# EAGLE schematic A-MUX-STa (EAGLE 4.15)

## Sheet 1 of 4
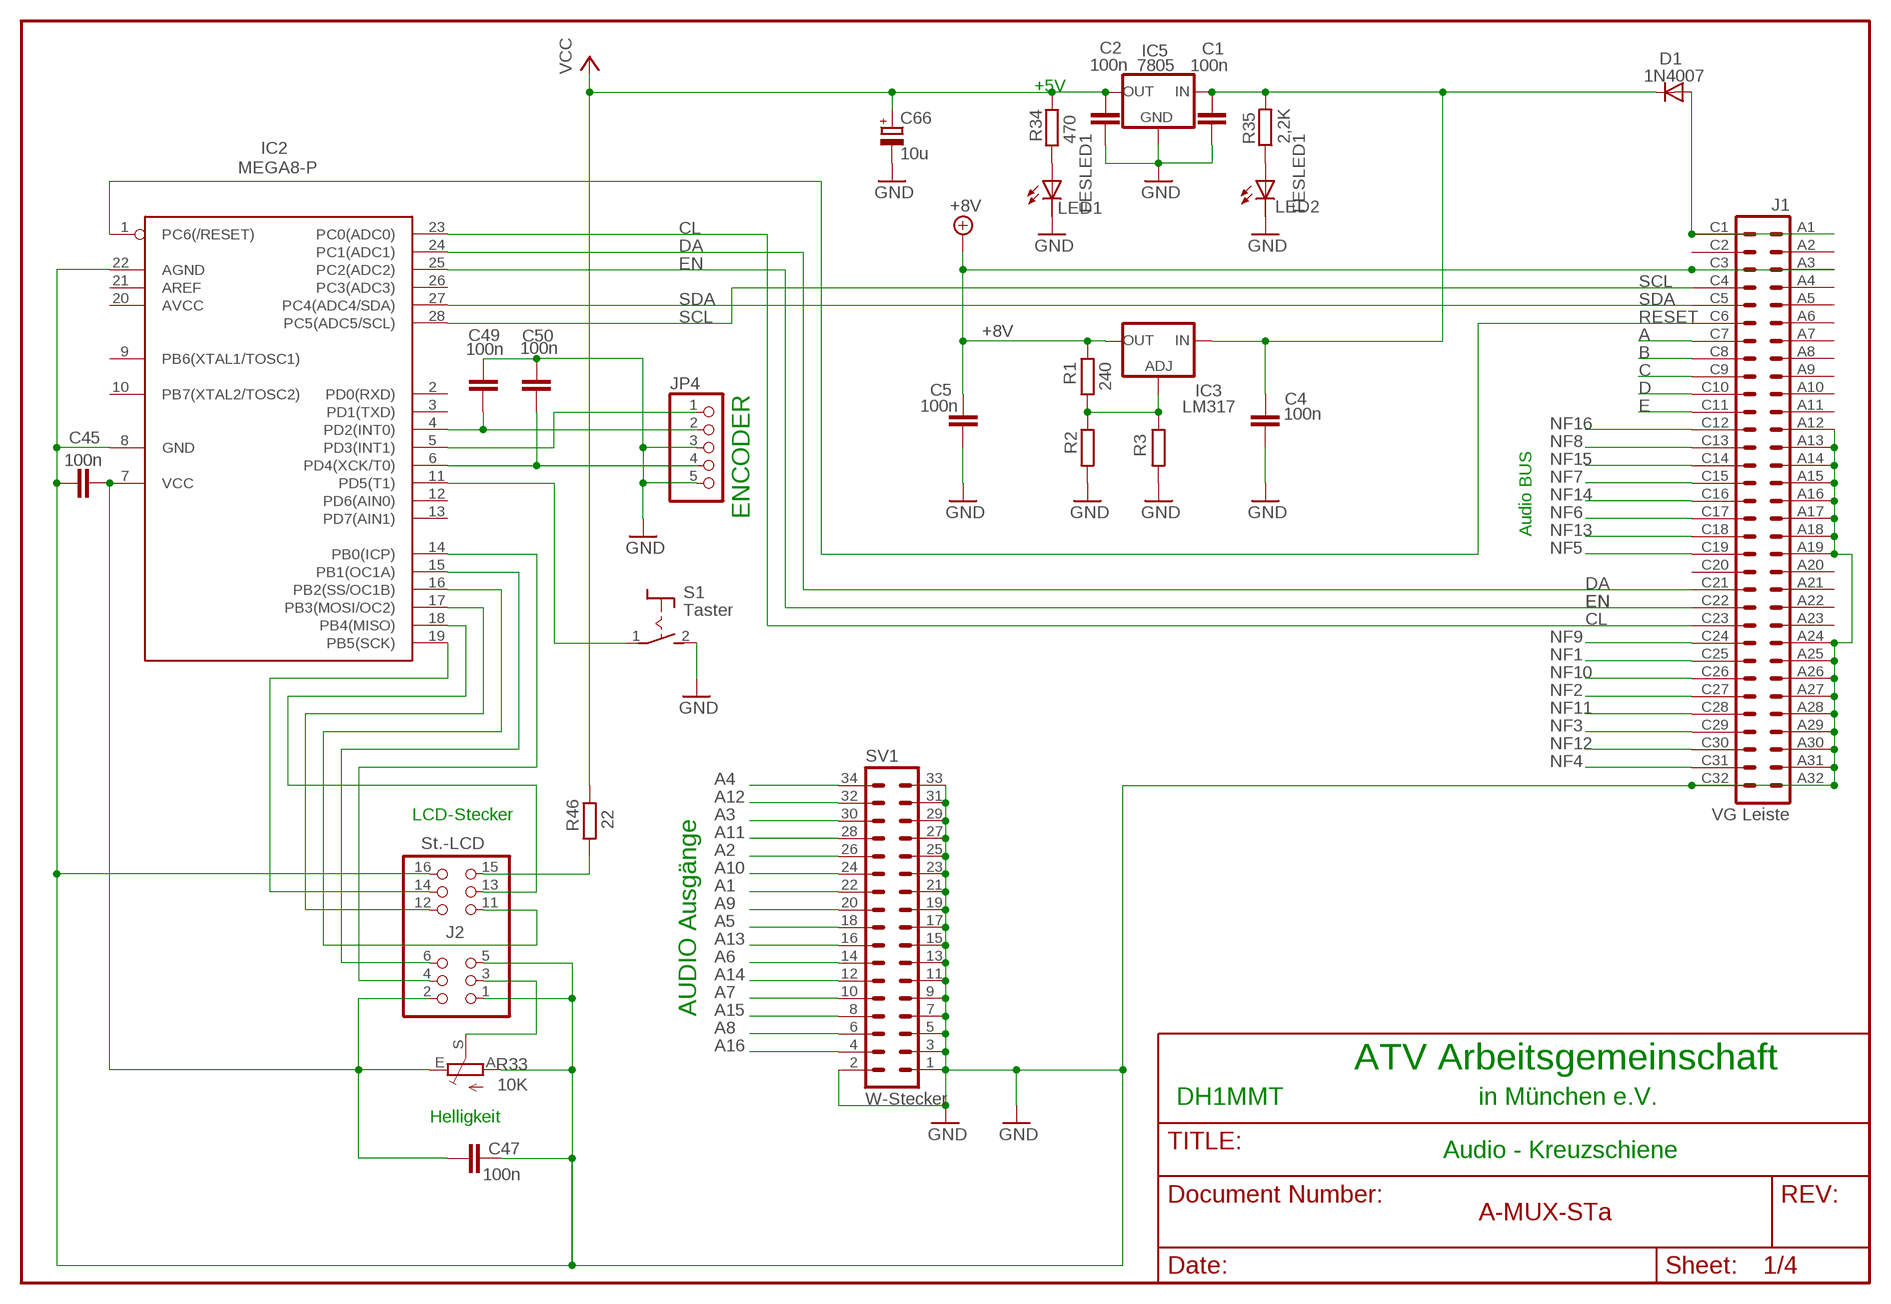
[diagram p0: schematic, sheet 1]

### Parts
C1  100n  C-EUC0805K  [C0805K]
C2  100n  C-EUC0805K  [C0805K]
C4  100n  C-EUC0805K  [C0805K]
C5  100n  C-EUC0805K  [C0805K]
C45  100n  C-EU025-024X044  [C025-024X044]
C47  100n  C-EU025-024X044  [C025-024X044]
C49  100n  C-EUC0805K  [C0805K]
C50  100n  C-EUC0805K  [C0805K]
C66  10u  CPOL-EUE2.5-5  [E2,5-5]
D1  1N4007  DIODE-D-7.5  [D-7.5]
IC2  MEGA8-P  [DIL28-3]
IC3  LM317  LM317TL  [317TL]
IC5  7805  78XXL  [78XXL]
J1  VG Leiste  VG64P  [VG64P]
J2  St.-LCD  PINHD2X3-2X3  [2X3-2X3]
JP4  PINHD-1X5  [1X05]
LED1  FESLED1  [FESLED1]
LED2  FESLED1  [FESLED1]
R1  240  R-EU_MELF0204W  [MINI_MELF-0204W]
R2  R-EU_MELF0204W  [MINI_MELF-0204W]
R3  R-EU_MELF0204W  [MINI_MELF-0204W]
R33  10K  TRIM_EU-CA6V  [CA6V]
R34  470  R-EU_0204/7  [0204/7]
R35  2,2K  R-EU_0204/7  [0204/7]
R46  22  R-EU_0204/7  [0204/7]
S1  Taster  MARQ  [MARQ]
SV1  W-Stecker  ML34  [ML34]

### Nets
+8V: C5.1 IC3.2(OUT) J1.A3 J1.C3 R1.1 ; also sheet 3,4
A: J1.C7
A1: SV1.22 ; also sheet 3
A2: SV1.26 ; also sheet 3
A3: SV1.30 ; also sheet 3
A4: SV1.34 ; also sheet 3
A5: SV1.18 ; also sheet 3
A6: SV1.14 ; also sheet 3
A7: SV1.10 ; also sheet 3
A8: SV1.6 ; also sheet 3
A9: SV1.20 ; also sheet 4
A10: SV1.24 ; also sheet 4
A11: SV1.28 ; also sheet 4
A12: SV1.32 ; also sheet 4
A13: SV1.16 ; also sheet 4
A14: SV1.12 ; also sheet 4
A15: SV1.8 ; also sheet 4
A16: SV1.4 ; also sheet 4
B: J1.C8
C: J1.C9
CL: IC2.23(PC0(ADC0)) J1.C23
D: J1.C10
DA: IC2.24(PC1(ADC1)) J1.C21
E: J1.C11
EN: IC2.25(PC2(ADC2)) J1.C22
GND: C1.2 C2.2 C4.2 C5.2 C45.1 C47.2 C49.1 C50.1 C66.- IC2.8(GND) IC2.22(AGND) IC5.GND J1.A12 J1.A13 J1.A14 J1.A15 J1.A16 J1.A17 J1.A18 J1.A19 J1.A24 J1.A25 J1.A26 J1.A27 J1.A28 J1.A29 J1.A30 J1.A31 J1.A32 J1.C32 J2.1 J2.5 J2.16 JP4.3 JP4.5 LED1.K(C) LED2.K(C) R2.2 R3.2 R33.A S1.2(S) SV1.1 SV1.2 SV1.3 SV1.5 SV1.7 SV1.9 SV1.11 SV1.13 SV1.15 SV1.17 SV1.19 SV1.21 SV1.23 SV1.25 SV1.27 SV1.29 SV1.31 SV1.33 ; also sheet 2,3,4
N$2: C1.1 C4.1 D1.C IC3.3(IN) IC5.IN R35.2
N$5: J2.15 R46.2
N$7: IC2.11(PD5(T1)) S1.1(P)
N$10: C49.2 IC2.4(PD2(INT0)) JP4.2
N$11: C50.2 IC2.6(PD4(XCK/T0)) JP4.4
N$12: D1.A J1.A1 J1.C1
N$15: IC3.1(ADJ) R1.2 R2.1 R3.1
N$56: IC2.15(PB1(OC1A)) J2.6
N$57: IC2.16(PB2(SS/OC1B)) J2.11
N$59: IC2.17(PB3(MOSI/OC2)) J2.12
N$61: IC2.18(PB4(MISO)) J2.13
N$62: IC2.19(PB5(SCK)) J2.14
N$70: LED1.A R34.2
N$89: J2.3 R33.S
N$91: LED2.A R35.1
N$142: IC2.14(PB0(ICP)) J2.4
N$236: IC2.5(PD3(INT1)) JP4.1
NF1: J1.C25 ; also sheet 3
NF2: J1.C27 ; also sheet 3
NF3: J1.C29 ; also sheet 3
NF4: J1.C31 ; also sheet 3
NF5: J1.C19 ; also sheet 3
NF6: J1.C17 ; also sheet 3
NF7: J1.C15 ; also sheet 3
NF8: J1.C13 ; also sheet 3
NF9: J1.C24 ; also sheet 4
NF10: J1.C26 ; also sheet 4
NF11: J1.C28 ; also sheet 4
NF12: J1.C30 ; also sheet 4
NF13: J1.C18 ; also sheet 4
NF14: J1.C16 ; also sheet 4
NF15: J1.C14 ; also sheet 4
NF16: J1.C12 ; also sheet 4
RESET: IC2.1(PC6(/RESET)) J1.C6
SCL: IC2.28(PC5(ADC5/SCL)) J1.C4 ; also sheet 2
SDA: IC2.27(PC4(ADC4/SDA)) J1.C5 ; also sheet 2
VCC: C2.1 C45.2 C47.1 C66.+ IC2.7(VCC) IC5.OUT J2.2 R33.E R34.1 R46.1 ; also sheet 2
Unconnected: IC2.2(PD0(RXD)) IC2.3(PD1(TXD)) IC2.9(PB6(XTAL1/TOSC1)) IC2.10(PB7(XTAL2/TOSC2)) IC2.12(PD6(AIN0)) IC2.13(PD7(AIN1)) IC2.20(AVCC) IC2.21(AREF) IC2.26(PC3(ADC3)) J1.A2 J1.A4 J1.A5 J1.A6 J1.A7 J1.A8 J1.A9 J1.A10 J1.A11 J1.A20 J1.A21 J1.A22 J1.A23 J1.C2 J1.C20

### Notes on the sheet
- +5V
- ENCODER
- Audio BUS
- LCD-Stecker
- AUDIO Ausgänge
- ATV Arbeitsgemeinschaft
- DH1MMT | in München e.V.
- Helligkeit
- Audio - Kreuzschiene

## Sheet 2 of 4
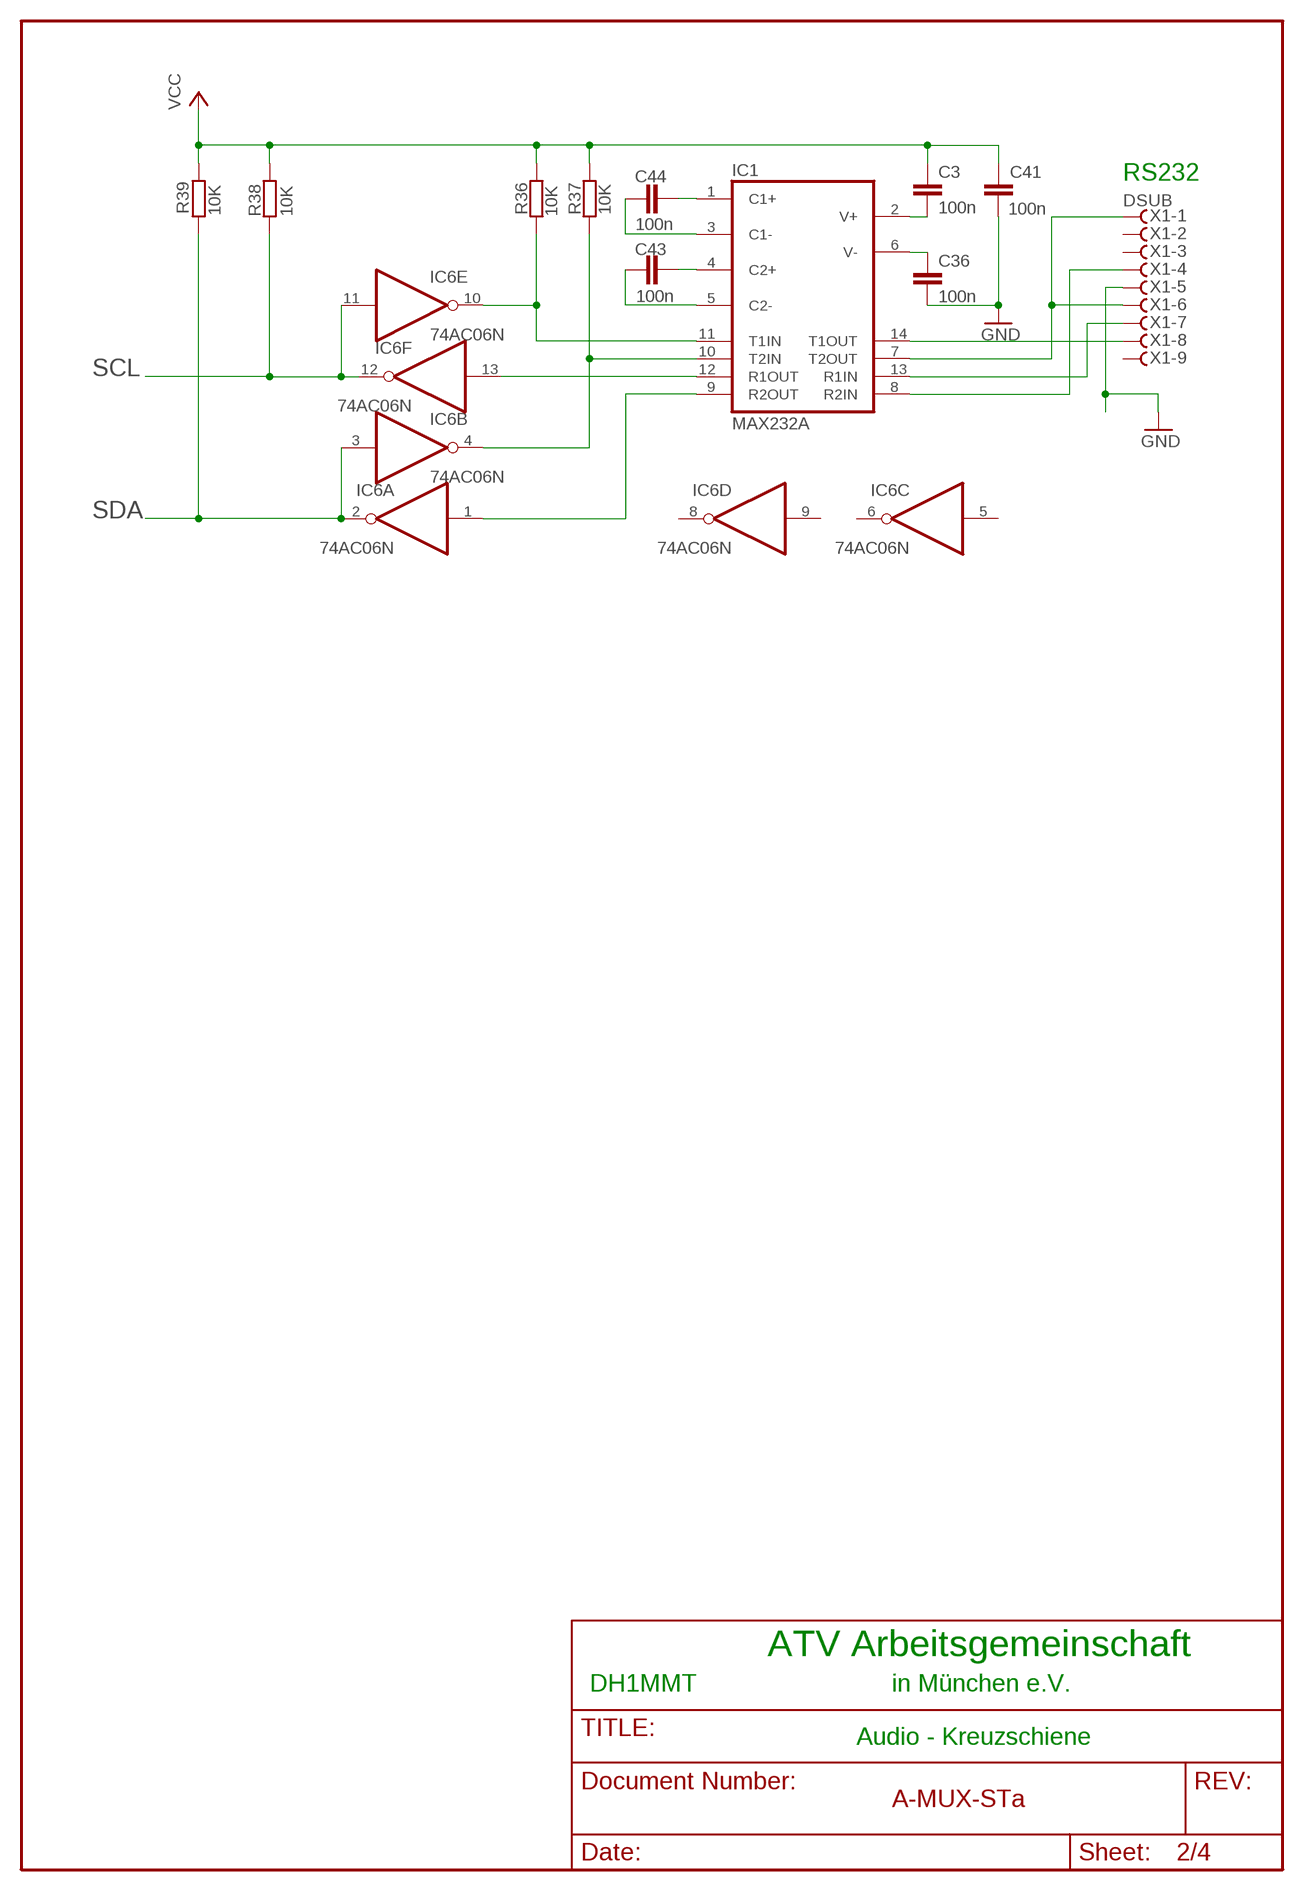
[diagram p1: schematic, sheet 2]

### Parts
C3  100n  C-EU050-024X044  [C050-024X044]
C36  100n  C-EU025-024X044  [C025-024X044]
C41  100n  C-EU050-024X044  [C050-024X044]
C43  100n  C-EU025-024X044  [C025-024X044]
C44  100n  C-EU050-024X044  [C050-024X044]
IC1  MAX232A  MAX232  [DIL16]
IC6  74AC06N  [DIL14]
R36  10K  R-EU_0204/7  [0204/7]
R37  10K  R-EU_0204/7  [0204/7]
R38  10K  R-EU_0204/7  [0204/7]
R39  10K  R-EU_0204/7  [0204/7]
X1  DSUB  F09HS  [F09H]

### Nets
GND: C36.2 C41.1 X1.5 ; also sheet 1,3,4
N$126: IC1.12(R1OUT) IC6.13(F:I)
N$127: C44.2 IC1.1(C1+)
N$129: C44.1 IC1.3(C1-)
N$130: C43.2 IC1.4(C2+)
N$131: C43.1 IC1.5(C2-)
N$132: C3.2 IC1.2(V+)
N$133: C36.1 IC1.6(V-)
N$134: IC1.9(R2OUT) IC6.1(A:I)
N$135: IC1.11(T1IN) IC6.10(E:O) R36.1
N$136: IC1.14(T1OUT) X1.8
N$137: IC1.13(R1IN) X1.7
N$138: IC1.8(R2IN) X1.4
N$139: IC1.7(T2OUT) X1.1 X1.6
N$145: IC1.10(T2IN) IC6.4(B:O) R37.1
SCL: IC6.11(E:I) IC6.12(F:O) R38.1 ; also sheet 1
SDA: IC6.2(A:O) IC6.3(B:I) R39.1 ; also sheet 1
VCC: C3.1 C41.2 R36.2 R37.2 R38.2 R39.2 ; also sheet 1
Unconnected: IC6.5(C:I) IC6.6(C:O) IC6.8(D:O) IC6.9(D:I) X1.2 X1.3 X1.9

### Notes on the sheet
- RS232
- ATV Arbeitsgemeinschaft
- DH1MMT | in München e.V.
- Audio - Kreuzschiene

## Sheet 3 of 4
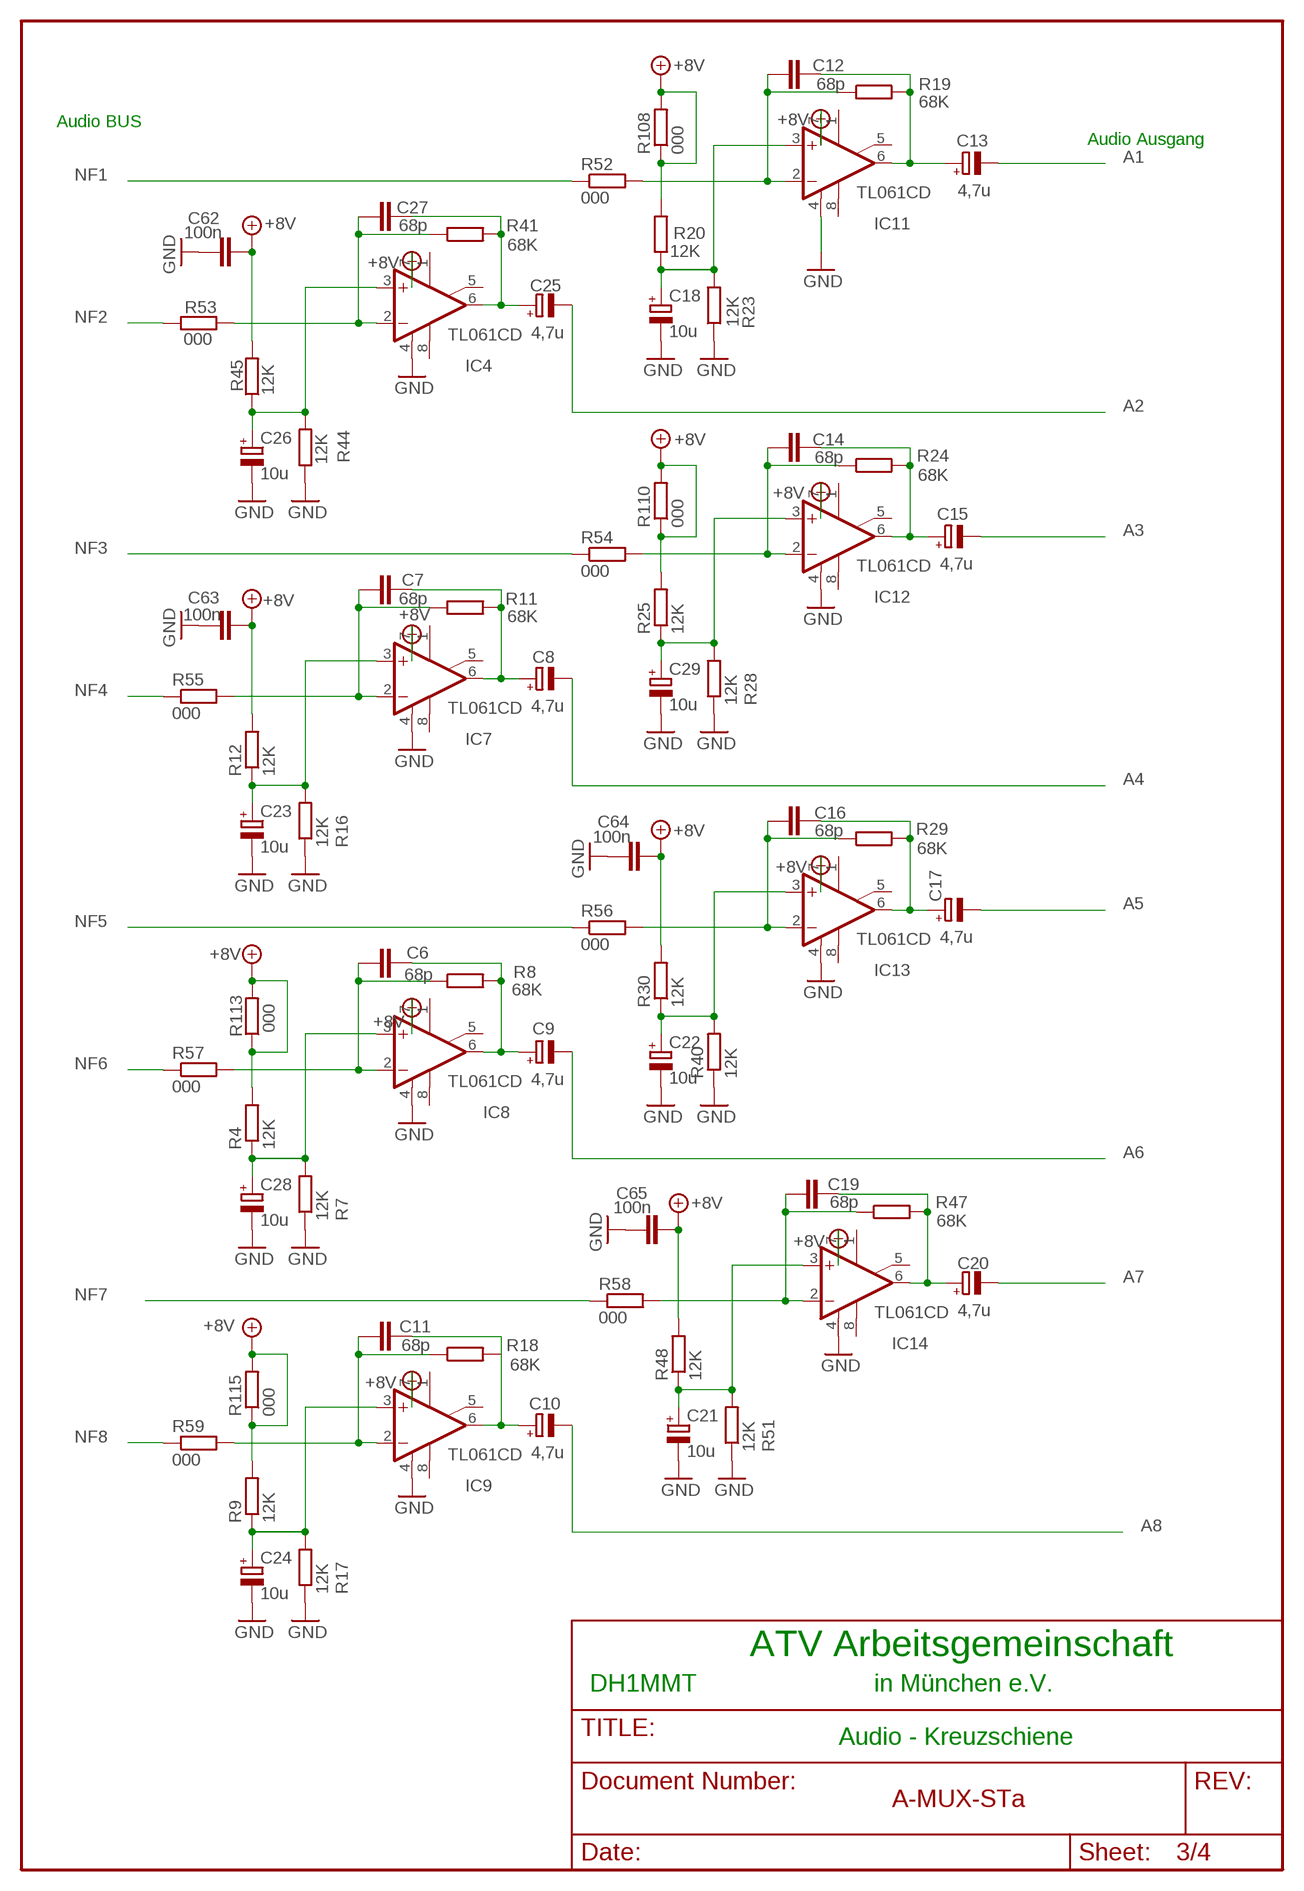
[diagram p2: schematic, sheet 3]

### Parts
C6  68p  C-EUC0805K  [C0805K]
C7  68p  C-EUC0805K  [C0805K]
C8  4,7u  CPOL-EUE2.5-5  [E2,5-5]
C9  4,7u  CPOL-EUE2.5-5  [E2,5-5]
C10  4,7u  CPOL-EUE2.5-5  [E2,5-5]
C11  68p  C-EUC0805K  [C0805K]
C12  68p  C-EUC0805K  [C0805K]
C13  4,7u  CPOL-EUE2.5-5  [E2,5-5]
C14  68p  C-EUC0805K  [C0805K]
C15  4,7u  CPOL-EUE2.5-5  [E2,5-5]
C16  68p  C-EUC0805K  [C0805K]
C17  4,7u  CPOL-EUE2.5-5  [E2,5-5]
C18  10u  CPOL-EUE2.5-5  [E2,5-5]
C19  68p  C-EUC0805K  [C0805K]
C20  4,7u  CPOL-EUE2.5-5  [E2,5-5]
C21  10u  CPOL-EUE2.5-5  [E2,5-5]
C22  10u  CPOL-EUE2.5-5  [E2,5-5]
C23  10u  CPOL-EUE2.5-5  [E2,5-5]
C24  10u  CPOL-EUE2.5-5  [E2,5-5]
C25  4,7u  CPOL-EUE2.5-5  [E2,5-5]
C26  10u  CPOL-EUE2.5-5  [E2,5-5]
C27  68p  C-EUC0805K  [C0805K]
C28  10u  CPOL-EUE2.5-5  [E2,5-5]
C29  10u  CPOL-EUE2.5-5  [E2,5-5]
C62  100n  C-EUC0805K  [C0805K]
C63  100n  C-EUC0805K  [C0805K]
C64  100n  C-EUC0805K  [C0805K]
C65  100n  C-EUC0805K  [C0805K]
IC4  TL061CD  TL061D  [SO08]
IC7  TL061CD  TL061D  [SO08]
IC8  TL061CD  TL061D  [SO08]
IC9  TL061CD  TL061D  [SO08]
IC11  TL061CD  TL061D  [SO08]
IC12  TL061CD  TL061D  [SO08]
IC13  TL061CD  TL061D  [SO08]
IC14  TL061CD  TL061D  [SO08]
R4  12K  R-EU_MELF0204W  [MINI_MELF-0204W]
R7  12K  R-EU_MELF0204W  [MINI_MELF-0204W]
R8  68K  R-EU_MELF0204W  [MINI_MELF-0204W]
R9  12K  R-EU_MELF0204W  [MINI_MELF-0204W]
R11  68K  R-EU_MELF0204W  [MINI_MELF-0204W]
R12  12K  R-EU_MELF0204W  [MINI_MELF-0204W]
R16  12K  R-EU_MELF0204W  [MINI_MELF-0204W]
R17  12K  R-EU_MELF0204W  [MINI_MELF-0204W]
R18  68K  R-EU_MELF0204W  [MINI_MELF-0204W]
R19  68K  R-EU_MELF0204W  [MINI_MELF-0204W]
R20  12K  R-EU_MELF0204W  [MINI_MELF-0204W]
R23  12K  R-EU_MELF0204W  [MINI_MELF-0204W]
R24  68K  R-EU_MELF0204W  [MINI_MELF-0204W]
R25  12K  R-EU_MELF0204W  [MINI_MELF-0204W]
R28  12K  R-EU_MELF0204W  [MINI_MELF-0204W]
R29  68K  R-EU_MELF0204W  [MINI_MELF-0204W]
R30  12K  R-EU_MELF0204W  [MINI_MELF-0204W]
R40  12K  R-EU_MELF0204W  [MINI_MELF-0204W]
R41  68K  R-EU_MELF0204W  [MINI_MELF-0204W]
R44  12K  R-EU_MELF0204W  [MINI_MELF-0204W]
R45  12K  R-EU_MELF0204W  [MINI_MELF-0204W]
R47  68K  R-EU_MELF0204W  [MINI_MELF-0204W]
R48  12K  R-EU_MELF0204W  [MINI_MELF-0204W]
R51  12K  R-EU_MELF0204W  [MINI_MELF-0204W]
R52  000  R-EU_MELF0204W  [MINI_MELF-0204W]
R53  000  R-EU_MELF0204W  [MINI_MELF-0204W]
R54  000  R-EU_MELF0204W  [MINI_MELF-0204W]
R55  000  R-EU_MELF0204W  [MINI_MELF-0204W]
R56  000  R-EU_MELF0204W  [MINI_MELF-0204W]
R57  000  R-EU_MELF0204W  [MINI_MELF-0204W]
R58  000  R-EU_MELF0204W  [MINI_MELF-0204W]
R59  000  R-EU_MELF0204W  [MINI_MELF-0204W]
R108  000  R-EU_MELF0204W  [MINI_MELF-0204W]
R110  000  R-EU_MELF0204W  [MINI_MELF-0204W]
R113  000  R-EU_MELF0204W  [MINI_MELF-0204W]
R115  000  R-EU_MELF0204W  [MINI_MELF-0204W]

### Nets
+8V: C62.2 C63.2 C64.2 C65.2 IC4.7(V+) IC7.7(V+) IC8.7(V+) IC9.7(V+) IC11.7(V+) IC12.7(V+) IC13.7(V+) IC14.7(V+) R4.2 R9.2 R12.2 R20.2 R25.2 R30.2 R45.2 R48.2 R108.1 R108.2 R110.1 R110.2 R113.1 R113.2 R115.1 R115.2 ; also sheet 1,4
A1: C13.- ; also sheet 1
A2: C25.- ; also sheet 1
A3: C15.- ; also sheet 1
A4: C8.- ; also sheet 1
A5: C17.- ; also sheet 1
A6: C9.- ; also sheet 1
A7: C20.- ; also sheet 1
A8: C10.- ; also sheet 1
GND: C18.- C21.- C22.- C23.- C24.- C26.- C28.- C29.- C62.1 C63.1 C64.1 C65.1 IC4.4(V-) IC7.4(V-) IC8.4(V-) IC9.4(V-) IC11.4(V-) IC12.4(V-) IC13.4(V-) IC14.4(V-) R7.1 R16.1 R17.1 R23.1 R28.1 R40.1 R44.1 R51.1 ; also sheet 1,2,4
N$9: C25.+ C27.2 IC4.6(OUT) R41.2
N$13: C7.2 C8.+ IC7.6(OUT) R11.2
N$14: C28.+ IC8.3(+IN) R4.1 R7.2
N$17: C6.1 IC8.2(-IN) R8.1 R57.2
N$18: C6.2 C9.+ IC8.6(OUT) R8.2
N$19: C24.+ IC9.3(+IN) R9.1 R17.2
N$20: C16.2 C17.+ IC13.6(OUT) R29.2
N$22: C16.1 IC13.2(-IN) R29.1 R56.2
N$24: C21.+ IC14.3(+IN) R48.1 R51.2
N$25: C19.2 C20.+ IC14.6(OUT) R47.2
N$27: C23.+ IC7.3(+IN) R12.1 R16.2
N$29: C10.+ C11.2 IC9.6(OUT) R18.2
N$35: C18.+ IC11.3(+IN) R20.1 R23.2
N$36: C12.2 C13.+ IC11.6(OUT) R19.2
N$37: C12.1 IC11.2(-IN) R19.1 R52.2
N$41: C29.+ IC12.3(+IN) R25.1 R28.2
N$42: C14.2 C15.+ IC12.6(OUT) R24.2
N$47: C22.+ IC13.3(+IN) R30.1 R40.2
N$84: C11.1 IC9.2(-IN) R18.1 R59.2
N$85: C27.1 IC4.2(-IN) R41.1 R53.2
N$97: C7.1 IC7.2(-IN) R11.1 R55.2
N$108: C14.1 IC12.2(-IN) R24.1 R54.2
N$110: C19.1 IC14.2(-IN) R47.1 R58.2
N$152: C26.+ IC4.3(+IN) R44.2 R45.1
NF1: R52.1 ; also sheet 1
NF2: R53.1 ; also sheet 1
NF3: R54.1 ; also sheet 1
NF4: R55.1 ; also sheet 1
NF5: R56.1 ; also sheet 1
NF6: R57.1 ; also sheet 1
NF7: R58.1 ; also sheet 1
NF8: R59.1 ; also sheet 1
Unconnected: IC4.1(ON1) IC4.5(ON2) IC4.8(OPT) IC7.1(ON1) IC7.5(ON2) IC7.8(OPT) IC8.1(ON1) IC8.5(ON2) IC8.8(OPT) IC9.1(ON1) IC9.5(ON2) IC9.8(OPT) IC11.1(ON1) IC11.5(ON2) IC11.8(OPT) IC12.1(ON1) IC12.5(ON2) IC12.8(OPT) IC13.1(ON1) IC13.5(ON2) IC13.8(OPT) IC14.1(ON1) IC14.5(ON2) IC14.8(OPT)

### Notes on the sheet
- Audio BUS
- Audio Ausgang
- ATV Arbeitsgemeinschaft
- DH1MMT | in München e.V.
- Audio - Kreuzschiene

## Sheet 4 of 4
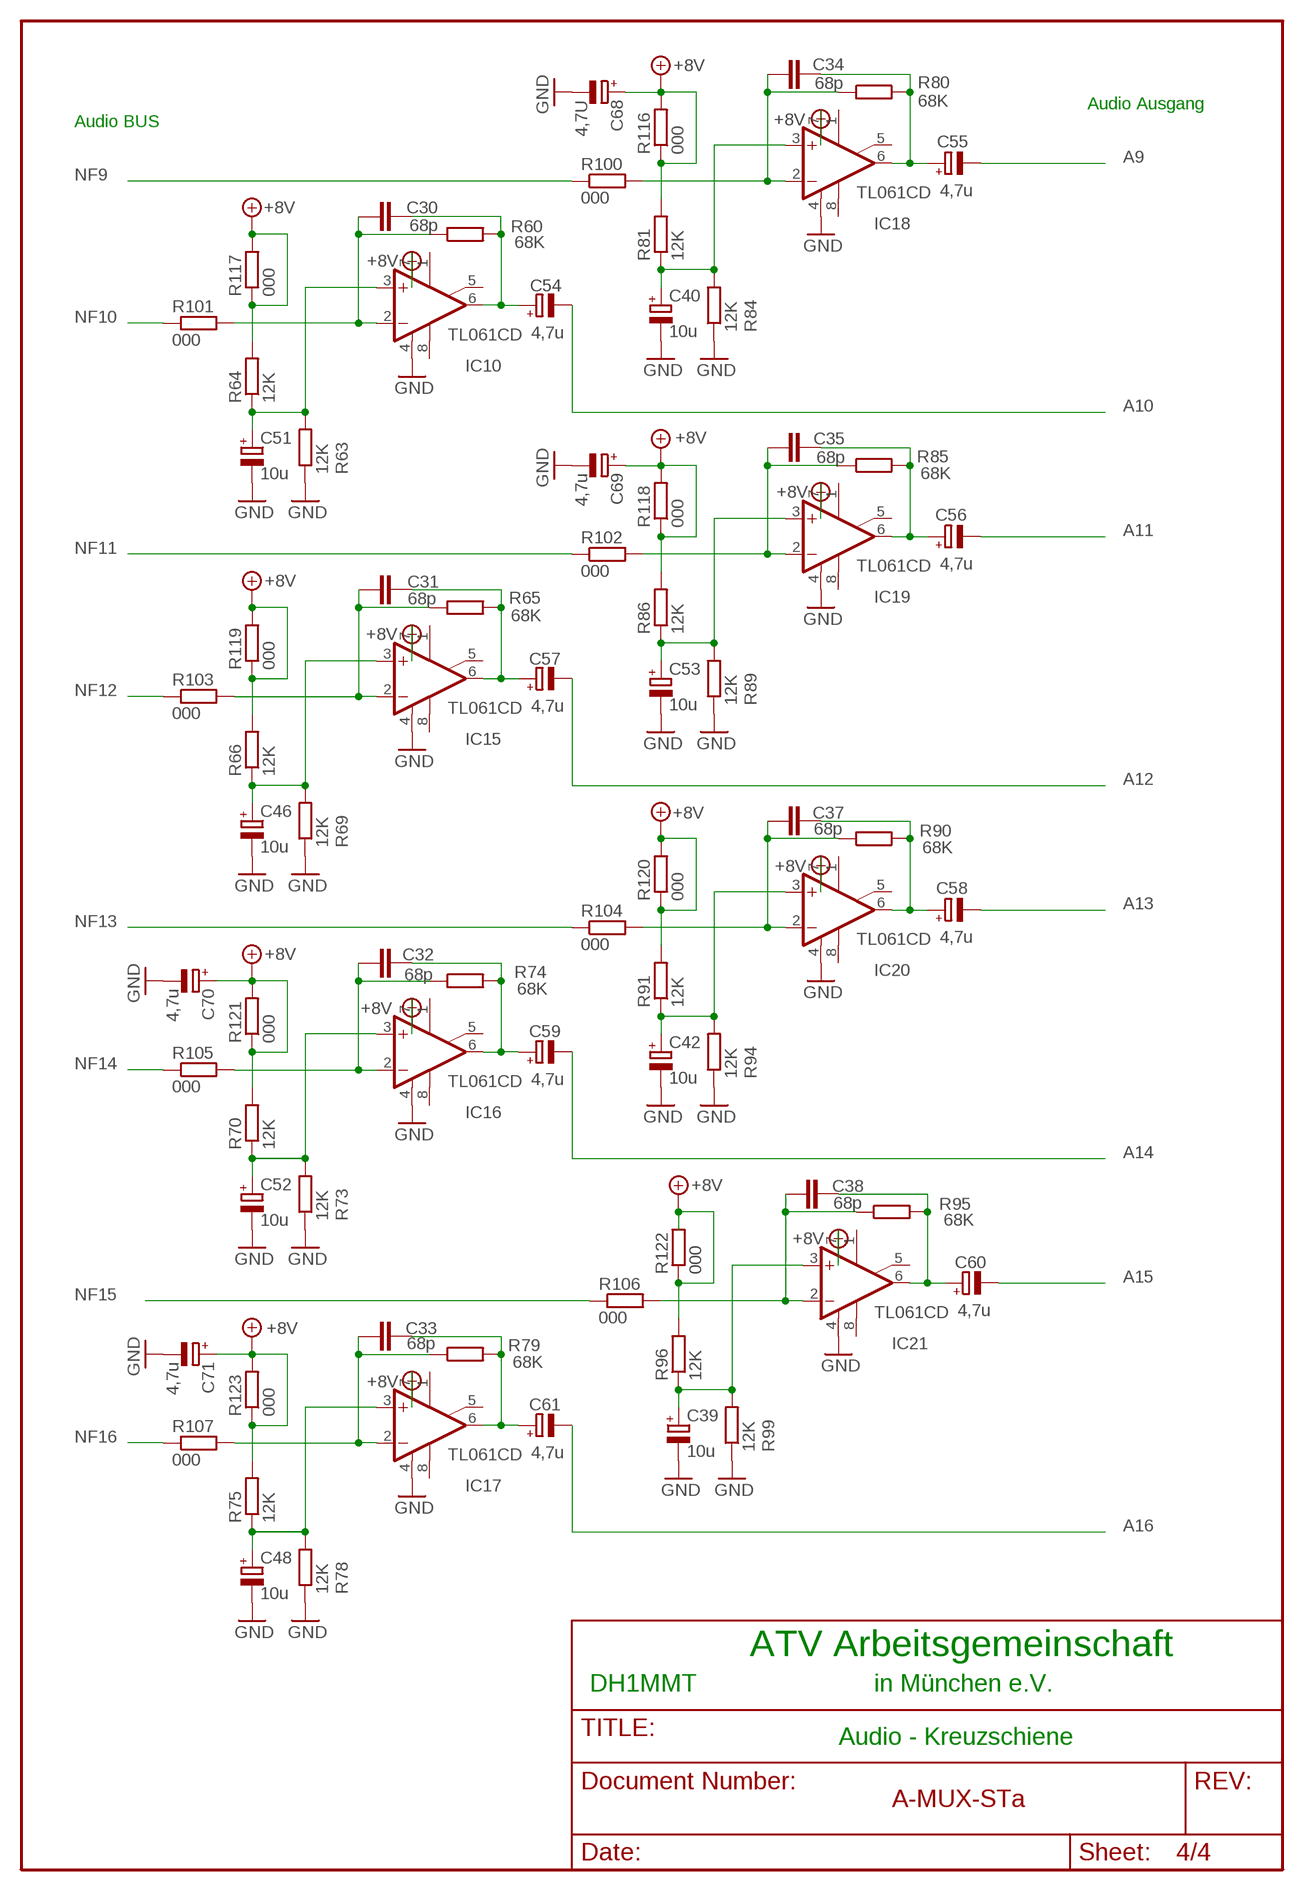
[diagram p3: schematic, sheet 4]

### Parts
C30  68p  C-EUC0805K  [C0805K]
C31  68p  C-EUC0805K  [C0805K]
C32  68p  C-EUC0805K  [C0805K]
C33  68p  C-EUC0805K  [C0805K]
C34  68p  C-EUC0805K  [C0805K]
C35  68p  C-EUC0805K  [C0805K]
C37  68p  C-EUC0805K  [C0805K]
C38  68p  C-EUC0805K  [C0805K]
C39  10u  CPOL-EUE2.5-5  [E2,5-5]
C40  10u  CPOL-EUE2.5-5  [E2,5-5]
C42  10u  CPOL-EUE2.5-5  [E2,5-5]
C46  10u  CPOL-EUE2.5-5  [E2,5-5]
C48  10u  CPOL-EUE2.5-5  [E2,5-5]
C51  10u  CPOL-EUE2.5-5  [E2,5-5]
C52  10u  CPOL-EUE2.5-5  [E2,5-5]
C53  10u  CPOL-EUE2.5-5  [E2,5-5]
C54  4,7u  CPOL-EUE2.5-5  [E2,5-5]
C55  4,7u  CPOL-EUE2.5-5  [E2,5-5]
C56  4,7u  CPOL-EUE2.5-5  [E2,5-5]
C57  4,7u  CPOL-EUE2.5-5  [E2,5-5]
C58  4,7u  CPOL-EUE2.5-5  [E2,5-5]
C59  4,7u  CPOL-EUE2.5-5  [E2,5-5]
C60  4,7u  CPOL-EUE2.5-5  [E2,5-5]
C61  4,7u  CPOL-EUE2.5-5  [E2,5-5]
C68  4,7U  CPOL-EUE1.8-4  [E1,8-4]
C69  4,7u  CPOL-EUE1.8-4  [E1,8-4]
C70  4,7u  CPOL-EUE1.8-4  [E1,8-4]
C71  4,7u  CPOL-EUE1.8-4  [E1,8-4]
IC10  TL061CD  TL061D  [SO08]
IC15  TL061CD  TL061D  [SO08]
IC16  TL061CD  TL061D  [SO08]
IC17  TL061CD  TL061D  [SO08]
IC18  TL061CD  TL061D  [SO08]
IC19  TL061CD  TL061D  [SO08]
IC20  TL061CD  TL061D  [SO08]
IC21  TL061CD  TL061D  [SO08]
R60  68K  R-EU_MELF0204W  [MINI_MELF-0204W]
R63  12K  R-EU_MELF0204W  [MINI_MELF-0204W]
R64  12K  R-EU_MELF0204W  [MINI_MELF-0204W]
R65  68K  R-EU_MELF0204W  [MINI_MELF-0204W]
R66  12K  R-EU_MELF0204W  [MINI_MELF-0204W]
R69  12K  R-EU_MELF0204W  [MINI_MELF-0204W]
R70  12K  R-EU_MELF0204W  [MINI_MELF-0204W]
R73  12K  R-EU_MELF0204W  [MINI_MELF-0204W]
R74  68K  R-EU_MELF0204W  [MINI_MELF-0204W]
R75  12K  R-EU_MELF0204W  [MINI_MELF-0204W]
R78  12K  R-EU_MELF0204W  [MINI_MELF-0204W]
R79  68K  R-EU_MELF0204W  [MINI_MELF-0204W]
R80  68K  R-EU_MELF0204W  [MINI_MELF-0204W]
R81  12K  R-EU_MELF0204W  [MINI_MELF-0204W]
R84  12K  R-EU_MELF0204W  [MINI_MELF-0204W]
R85  68K  R-EU_MELF0204W  [MINI_MELF-0204W]
R86  12K  R-EU_MELF0204W  [MINI_MELF-0204W]
R89  12K  R-EU_MELF0204W  [MINI_MELF-0204W]
R90  68K  R-EU_MELF0204W  [MINI_MELF-0204W]
R91  12K  R-EU_MELF0204W  [MINI_MELF-0204W]
R94  12K  R-EU_MELF0204W  [MINI_MELF-0204W]
R95  68K  R-EU_MELF0204W  [MINI_MELF-0204W]
R96  12K  R-EU_MELF0204W  [MINI_MELF-0204W]
R99  12K  R-EU_MELF0204W  [MINI_MELF-0204W]
R100  000  R-EU_MELF0204W  [MINI_MELF-0204W]
R101  000  R-EU_MELF0204W  [MINI_MELF-0204W]
R102  000  R-EU_MELF0204W  [MINI_MELF-0204W]
R103  000  R-EU_MELF0204W  [MINI_MELF-0204W]
R104  000  R-EU_MELF0204W  [MINI_MELF-0204W]
R105  000  R-EU_MELF0204W  [MINI_MELF-0204W]
R106  000  R-EU_MELF0204W  [MINI_MELF-0204W]
R107  000  R-EU_MELF0204W  [MINI_MELF-0204W]
R116  000  R-EU_MELF0204W  [MINI_MELF-0204W]
R117  000  R-EU_MELF0204W  [MINI_MELF-0204W]
R118  000  R-EU_MELF0204W  [MINI_MELF-0204W]
R119  000  R-EU_MELF0204W  [MINI_MELF-0204W]
R120  000  R-EU_MELF0204W  [MINI_MELF-0204W]
R121  000  R-EU_MELF0204W  [MINI_MELF-0204W]
R122  000  R-EU_MELF0204W  [MINI_MELF-0204W]
R123  000  R-EU_MELF0204W  [MINI_MELF-0204W]

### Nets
+8V: C68.+ C69.+ C70.+ C71.+ IC10.7(V+) IC15.7(V+) IC16.7(V+) IC17.7(V+) IC18.7(V+) IC19.7(V+) IC20.7(V+) IC21.7(V+) R64.2 R66.2 R70.2 R75.2 R81.2 R86.2 R91.2 R96.2 R116.1 R116.2 R117.1 R117.2 R118.1 R118.2 R119.1 R119.2 R120.1 R120.2 R121.1 R121.2 R122.1 R122.2 R123.1 R123.2 ; also sheet 1,3
A9: C55.- ; also sheet 1
A10: C54.- ; also sheet 1
A11: C56.- ; also sheet 1
A12: C57.- ; also sheet 1
A13: C58.- ; also sheet 1
A14: C59.- ; also sheet 1
A15: C60.- ; also sheet 1
A16: C61.- ; also sheet 1
GND: C39.- C40.- C42.- C46.- C48.- C51.- C52.- C53.- C68.- C69.- C70.- C71.- IC10.4(V-) IC15.4(V-) IC16.4(V-) IC17.4(V-) IC18.4(V-) IC19.4(V-) IC20.4(V-) IC21.4(V-) R63.1 R69.1 R73.1 R78.1 R84.1 R89.1 R94.1 R99.1 ; also sheet 1,2,3
N$30: C30.1 IC10.2(-IN) R60.1 R101.2
N$31: C51.+ IC10.3(+IN) R63.2 R64.1
N$32: C30.2 C54.+ IC10.6(OUT) R60.2
N$33: C46.+ IC15.3(+IN) R66.1 R69.2
N$38: C31.2 C57.+ IC15.6(OUT) R65.2
N$39: C31.1 IC15.2(-IN) R65.1 R103.2
N$40: C52.+ IC16.3(+IN) R70.1 R73.2
N$44: C32.1 IC16.2(-IN) R74.1 R105.2
N$45: C32.2 C59.+ IC16.6(OUT) R74.2
N$46: C48.+ IC17.3(+IN) R75.1 R78.2
N$49: C33.2 C61.+ IC17.6(OUT) R79.2
N$50: C33.1 IC17.2(-IN) R79.1 R107.2
N$52: C40.+ IC18.3(+IN) R81.1 R84.2
N$53: C34.2 C55.+ IC18.6(OUT) R80.2
N$54: C34.1 IC18.2(-IN) R80.1 R100.2
N$55: C53.+ IC19.3(+IN) R86.1 R89.2
N$65: C35.2 C56.+ IC19.6(OUT) R85.2
N$66: C35.1 IC19.2(-IN) R85.1 R102.2
N$74: C42.+ IC20.3(+IN) R91.1 R94.2
N$75: C37.2 C58.+ IC20.6(OUT) R90.2
N$77: C37.1 IC20.2(-IN) R90.1 R104.2
N$78: C39.+ IC21.3(+IN) R96.1 R99.2
N$79: C38.2 C60.+ IC21.6(OUT) R95.2
N$83: C38.1 IC21.2(-IN) R95.1 R106.2
NF9: R100.1 ; also sheet 1
NF10: R101.1 ; also sheet 1
NF11: R102.1 ; also sheet 1
NF12: R103.1 ; also sheet 1
NF13: R104.1 ; also sheet 1
NF14: R105.1 ; also sheet 1
NF15: R106.1 ; also sheet 1
NF16: R107.1 ; also sheet 1
Unconnected: IC10.1(ON1) IC10.5(ON2) IC10.8(OPT) IC15.1(ON1) IC15.5(ON2) IC15.8(OPT) IC16.1(ON1) IC16.5(ON2) IC16.8(OPT) IC17.1(ON1) IC17.5(ON2) IC17.8(OPT) IC18.1(ON1) IC18.5(ON2) IC18.8(OPT) IC19.1(ON1) IC19.5(ON2) IC19.8(OPT) IC20.1(ON1) IC20.5(ON2) IC20.8(OPT) IC21.1(ON1) IC21.5(ON2) IC21.8(OPT)

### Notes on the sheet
- Audio Ausgang
- Audio BUS
- ATV Arbeitsgemeinschaft
- DH1MMT | in München e.V.
- Audio - Kreuzschiene

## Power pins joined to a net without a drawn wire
GND: IC1.15(GND) IC6.7(P:GND)
VCC: IC1.16(VCC) IC6.14(P:VCC)

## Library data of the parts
C1-C7 C11 C12 C14 C16 C19 C27 C30-C38 C41 C43-C45 C47 C49 C50 C62-C65 = rcl:C-EU: CAPACITOR, European symbol
C8-C10 C13 C15 C17 C18 C20-C26 C28 C29 C39 C40 C42 C46 C48 C51-C61 C66 C68-C71 = rcl:CPOL-EU: POLARIZED CAPACITOR, European symbol
D1 = diode:DIODE-: DIODE
IC1 = maxim:MAX232: RS232 TRANSEIVER
IC2 = avr:MEGA8-P: MICROCONTROLLER 8 Kbytes FLASH 1 kbytes SRAM 512 bytes EEPROM USART 4-channel 10 bit ADC 2-channel 8 bit ADC
IC3 = v-reg:LM317TL: VOLTAGE REGULATOR
IC4 IC7-IC21 = linear:TL061: OP AMP
IC5 = v-reg:78XXL: VOLTAGE REGULATOR
IC6 = 74xx-eu:74*06: Hex INVERTER, open collector high-voltage output
J1 = 19inch:VG64: PCB EUROCARD, 64-pin type C/AC, 2.54 mm
J2 = pinhead:PINHD2X3-2X3
JP4 = pinhead:PINHD-1X5: PIN HEADER
LED1 LED2 = led:FESLED1
R1-R4 R7-R9 R11 R12 R16-R20 R23-R25 R28-R30 R34-R41 R44-R48 R51-R60 R63-R66 R69 R70 R73-R75 R78-R81 R84-R86 R89-R91 R94-R96 R99-R108 R110 R113 R115-R123 = rcl:R-EU_: RESISTOR, European symbol
R33 = pot:TRIM_EU-: POTENTIOMETER
S1 = switch:MARQ
SV1 = con-harting-ml:ML34: HARTING
X1 = con-subd:F09?S: SUB-D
